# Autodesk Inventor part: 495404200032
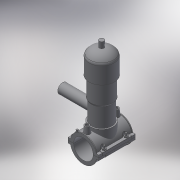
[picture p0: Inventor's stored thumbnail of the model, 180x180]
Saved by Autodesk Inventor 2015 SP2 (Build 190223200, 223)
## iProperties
Created: 2017-07
Part Number: 495404200032
Material: Generic
Description: PLASSON TAPPING VALVE 200-32
Document SubType Name: Modeling
Designer: KIM
Density: 1 g/cm^3
Appearance: Default
Author: KIM
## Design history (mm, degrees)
derived "495404-4954S4.ipt"
feature "Solid1::495404-4954S4.ipt"
feature "Solid2::495404-4954S4.ipt"
tag "TaggingFeature1"
body "Solid1"
body "Solid2"
other parameters: "d2" = 262.6, "d4" = 176, "d5" = 0, "d6" = 0.1, "d8" = 0, "d19" = 6, "d20" = 6, "d21" = 105.6, "d23" = 0, "d24" = 52.8, "d26" = 0, "d27" = 3, "d28" = 3, "d29" = 3, "d30" = 66.66667, "d31" = 6, "d32" = 0, "d33" = 0, "d34" = 0.6, "d40" = 121.68, "d47" = 163, "d70" = 15, "d72" = 0, "d73" = 6, "d75" = 5, "d76" = 0, "d79" = 15, "d80" = 70.4, "d82" = 5 deg, "d84" = 4, "d85" = 14, "d86" = 0, "d87" = 3, "d88" = 0, "d89" = 1, "d90" = 1, "d91" = 140.8, "d92" = 0, "d93" = 0.5, "d94" = 105.26316, "d96" = 241.02, "d97" = 3.52, "d98" = 0, "d120" = 140 deg, "d121" = 24.228, "d122" = 20 deg, "d123" = 468, "d124" = 140.4, "d126" = 0, "d143" = 206, "d145" = 26.15385, "d149" = 3, "d150" = 28.76923, "d153" = 176, "d154" = 0, "d156" = 117, "d157" = 160 deg, "d159" = 6.8, "d161" = 3, "d162" = 105.6, "d163" = 0, "d168" = 114.14634, "d170" = 3, "d172" = 0, "d173" = 1, "d176" = 20 deg, "d177" = 14, "d178" = 34, "d180" = 0, "d183" = 13.6, "d184" = 11.2, "d185" = 57.2, "d186" = 57.2, "d187" = 117, "d188" = 10.2, "d189" = 14, "d190" = 0, "d191" = 175.5, "d193" = 6.8, "d194" = 4.4, "d195" = 90 deg, "d197" = 0, "d199" = 0, "d205" = 14.64, "d206" = 81.33333, "d207" = 244, "d208" = 224.48, "d209" = 207.4, "d210" = 200.08, "d211" = 146.4, "d212" = 85.4, "d213" = 65.88, "d214" = 73.2, "d216" = 21.96, "d217" = 70.76, "d218" = 80.52, "d222" = 0, "d223" = 234, "d224" = 126, "d225" = 46, "d226" = 32, "d229" = 126, "d230" = 0, "B_" = 202, "H_" = 126, "L_" = 176, "d_t" = 6, "d_1" = 32, "H_1" = 46, "H_2" = 244, "d148" = 3, "d160" = 3, "d169" = 3, "d192" = 6.8, "d228" = 25.6
